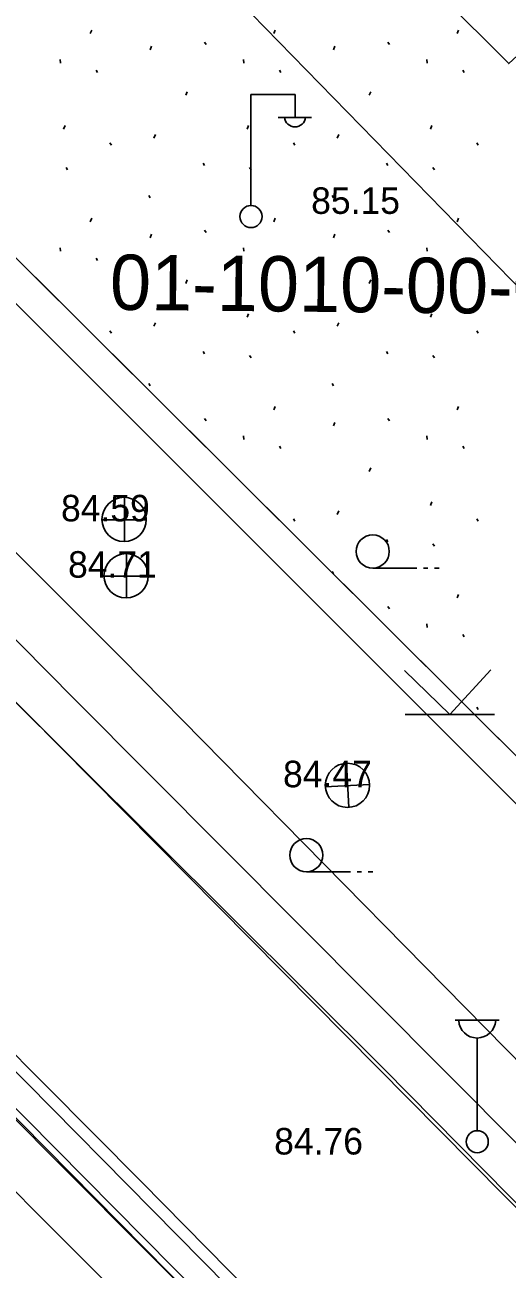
# Model space of a CAD drawing. Extents: x 412225 to 413380, y 4456471 to 4457189.
# Drawn here: x 412345.5 to 412367.3, y 4457046.4 to 4457102.7 of the extents above; entities that cross this region are included whole.
import ezdxf

# ---------------------------------------------------------------- set-up
doc = ezdxf.new("R2010")
doc.units = 0
for name, color, linetype in [('0_HALİHAZIR', 7, 'Continuous'), ('0_KADASTRO', 7, 'Continuous'), ('Level 27', 7, 'Continuous'), ('Level 41', 7, 'Continuous'), ('Level 56', 7, 'Continuous'), ('Level 57', 7, 'Continuous'), ('Level 62', 7, 'Continuous'), ('Level 8', 7, 'Continuous')]:
    doc.layers.add(name, color=color, linetype=linetype)

msp = doc.modelspace()

# ---------------------------------------------------------------- linework, layer by layer
at = {"layer": '0_HALİHAZIR'}
for p, q in [((412355.691, 4457094.546), (412355.691, 4457099.546)), ((412355.691, 4457099.546), (412357.691, 4457099.546)), ((412357.691, 4457098.546), (412357.691, 4457099.546)), ((412356.931, 4457098.506), (412358.431, 4457098.506)), ((412349.974, 4457079.31), (412349.974, 4457081.31)), ((412348.954, 4457080.3), (412350.954, 4457080.3)), ((412350.065, 4457076.761), (412350.065, 4457078.761)), ((412349.045, 4457077.751), (412351.045, 4457077.751)), ((412361.206, 4457078.12), (412363.206, 4457078.12)), ((412363.506, 4457078.12), (412363.706, 4457078.12)), ((412364.006, 4457078.12), (412364.206, 4457078.12)), ((412364.697, 4457071.497), (412362.637, 4457073.487)), ((412364.697, 4457071.497), (412366.547, 4457073.507)), ((412362.677, 4457071.497), (412366.717, 4457071.497)), ((412360.131, 4457067.283), (412360.025, 4457069.28)), ((412359.06, 4457068.218), (412361.057, 4457068.324)), ((412358.204, 4457064.381), (412360.204, 4457064.381)), ((412360.504, 4457064.381), (412360.704, 4457064.381)), ((412361.004, 4457064.381), (412361.204, 4457064.381)), ((412364.931, 4457057.666), (412366.931, 4457057.666)), ((412365.931, 4457052.666), (412365.931, 4457056.859))]:
    msp.add_line(p, q, dxfattribs=at)
for points in [[(412301.706, 4457121.318), (412311.102, 4457113.16), (412330.158, 4457093.729), (412349.865, 4457074.031), (412372.694, 4457050.81), (412390.772, 4457032.428), (412419.372, 4457004.721)], [(412406.259, 4456994.837), (412377.363, 4457023.335), (412350.75, 4457050.347), (412307.137, 4457094.27), (412284.187, 4457117.727)], [(412644.931, 4456753.555), (412630.555, 4456767.782), (412604.684, 4456793.709), (412582.154, 4456816.287), (412559.135, 4456839.628), (412534.75, 4456864.124), (412499.888, 4456899.345), (412487.433, 4456911.736), (412459.99, 4456939.333), (412440.337, 4456959.115), (412419.902, 4456979.921), (412392.691, 4457007.039), (412362.588, 4457037.58), (412334.209, 4457066.321), (412297.701, 4457103.437), (412284.18, 4457117.149)], [(412417.329, 4457002.236), (412381.395, 4457038.35), (412347.738, 4457072.166), (412303.554, 4457116.902)], [(412284.17, 4457116.265), (412296.803, 4457102.771), (412316.426, 4457082.291), (412338.061, 4457060.18), (412363.233, 4457034.899), (412383.867, 4457014.022), (412425.083, 4456972.499), (412446.131, 4456951.075), (412463.226, 4456933.647), (412501.75, 4456894.857), (412523.558, 4456872.918), (412554.446, 4456842.344)], [(412284.13, 4457112.788), (412289.83, 4457106.958), (412301.261, 4457094.649), (412314.468, 4457080.886), (412326.161, 4457068.858), (412338.147, 4457056.814), (412352.735, 4457042.191), (412364.851, 4457029.813), (412379.023, 4457015.687), (412394.281, 4457000.11), (412414.019, 4456980.608)], [(412422.853, 4457032.641), (412406.136, 4457050.742), (412389.41, 4457068.66), (412371.176, 4457087.358), (412353.875, 4457105.109)], [(412340.966, 4457076.102), (412361.717, 4457055.451), (412377.534, 4457039.414), (412399.513, 4457017.111), (412417.007, 4456999.535), (412433.199, 4456983.611)]]:
    msp.add_lwpolyline(points, dxfattribs=at)
for centre, radius in [((412355.701, 4457094.021), 0.5), ((412349.959, 4457080.318), 1), ((412361.206, 4457078.87), 0.75), ((412350.05, 4457077.769), 1), ((412360.062, 4457068.289), 1), ((412358.204, 4457065.131), 0.75), ((412365.931, 4457052.166), 0.5)]:
    msp.add_circle(centre, radius, dxfattribs=at)
for centre, radius, start, end in [((412357.691, 4457098.55), 0.474, 184.8384, 355.1464), ((412365.931, 4457057.695), 0.837, 183.298, 356.9072)]:
    msp.add_arc(centre, radius, start, end, dxfattribs=at)
at = {"layer": '0_KADASTRO'}
msp.add_lwpolyline([(412531.386, 4456906.626), (412255.662, 4457181.172)], dxfattribs=at)
at = {"layer": 'Level 27'}
msp.add_line((412531.386, 4456906.626), (412255.662, 4457181.172), dxfattribs=at)
at = {"layer": 'Level 41'}
for p, q in [((412348.434, 4457102.294), (412348.505, 4457102.453)), ((412356.727, 4457102.294), (412356.798, 4457102.453)), ((412365.02, 4457102.294), (412365.091, 4457102.453)), ((412353.598, 4457101.91), (412353.669, 4457101.803)), ((412361.891, 4457101.91), (412361.962, 4457101.803)), ((412351.133, 4457101.565), (412351.205, 4457101.725)), ((412359.426, 4457101.565), (412359.498, 4457101.725)), ((412347.063, 4457101.119), (412347.081, 4457100.959)), ((412355.356, 4457101.119), (412355.374, 4457100.959)), ((412363.649, 4457101.119), (412363.667, 4457100.959)), ((412348.693, 4457100.649), (412348.763, 4457100.542)), ((412356.986, 4457100.649), (412357.056, 4457100.542)), ((412365.279, 4457100.649), (412365.349, 4457100.542)), ((412352.749, 4457099.505), (412352.821, 4457099.665)), ((412361.042, 4457099.505), (412361.114, 4457099.665)), ((412347.228, 4457097.975), (412347.298, 4457098.135)), ((412355.521, 4457097.975), (412355.591, 4457098.135)), ((412363.814, 4457097.975), (412363.884, 4457098.135)), ((412349.323, 4457097.359), (412349.394, 4457097.253)), ((412351.311, 4457097.567), (412351.382, 4457097.727)), ((412357.616, 4457097.359), (412357.687, 4457097.253)), ((412359.604, 4457097.567), (412359.675, 4457097.727)), ((412365.909, 4457097.359), (412365.98, 4457097.253)), ((412347.337, 4457096.238), (412347.408, 4457096.131)), ((412353.531, 4457096.43), (412353.602, 4457096.323)), ((412355.63, 4457096.238), (412355.701, 4457096.131)), ((412361.824, 4457096.43), (412361.895, 4457096.323)), ((412363.923, 4457096.238), (412363.994, 4457096.131)), ((412351.075, 4457094.977), (412351.146, 4457094.87)), ((412359.368, 4457094.977), (412359.439, 4457094.87)), ((412348.434, 4457093.784), (412348.505, 4457093.943)), ((412356.727, 4457093.784), (412356.798, 4457093.943)), ((412365.02, 4457093.784), (412365.091, 4457093.943)), ((412351.133, 4457093.055), (412351.205, 4457093.215)), ((412353.598, 4457093.4), (412353.669, 4457093.293)), ((412359.426, 4457093.055), (412359.498, 4457093.215)), ((412361.891, 4457093.4), (412361.962, 4457093.293)), ((412347.063, 4457092.609), (412347.081, 4457092.449)), ((412355.356, 4457092.609), (412355.374, 4457092.449)), ((412363.649, 4457092.609), (412363.667, 4457092.449)), ((412348.693, 4457092.139), (412348.763, 4457092.032)), ((412356.986, 4457092.139), (412357.056, 4457092.032)), ((412365.279, 4457092.139), (412365.349, 4457092.032)), ((412352.749, 4457090.995), (412352.821, 4457091.155)), ((412361.042, 4457090.995), (412361.114, 4457091.155)), ((412355.521, 4457089.465), (412355.591, 4457089.625)), ((412363.814, 4457089.465), (412363.884, 4457089.625)), ((412351.311, 4457089.057), (412351.382, 4457089.217)), ((412359.604, 4457089.057), (412359.675, 4457089.217)), ((412349.323, 4457088.849), (412349.394, 4457088.743)), ((412357.616, 4457088.849), (412357.687, 4457088.743)), ((412365.909, 4457088.849), (412365.98, 4457088.743)), ((412353.531, 4457087.92), (412353.602, 4457087.813)), ((412361.824, 4457087.92), (412361.895, 4457087.813)), ((412355.63, 4457087.728), (412355.701, 4457087.621)), ((412363.923, 4457087.728), (412363.994, 4457087.621)), ((412351.075, 4457086.467), (412351.146, 4457086.36)), ((412359.368, 4457086.467), (412359.439, 4457086.36)), ((412356.727, 4457085.274), (412356.798, 4457085.433)), ((412365.02, 4457085.274), (412365.091, 4457085.433)), ((412353.598, 4457084.89), (412353.669, 4457084.783)), ((412359.426, 4457084.545), (412359.498, 4457084.705)), ((412361.891, 4457084.89), (412361.962, 4457084.783)), ((412355.356, 4457084.099), (412355.374, 4457083.939)), ((412363.649, 4457084.099), (412363.667, 4457083.939)), ((412356.986, 4457083.629), (412357.056, 4457083.522)), ((412365.279, 4457083.629), (412365.349, 4457083.522)), ((412361.042, 4457082.485), (412361.114, 4457082.645)), ((412363.814, 4457080.955), (412363.884, 4457081.115)), ((412359.604, 4457080.547), (412359.675, 4457080.707)), ((412357.616, 4457080.339), (412357.687, 4457080.233)), ((412365.909, 4457080.339), (412365.98, 4457080.233)), ((412361.824, 4457079.41), (412361.895, 4457079.303)), ((412363.923, 4457079.218), (412363.994, 4457079.111)), ((412359.368, 4457077.957), (412359.439, 4457077.85)), ((412365.02, 4457076.764), (412365.091, 4457076.923)), ((412361.891, 4457076.38), (412361.962, 4457076.273)), ((412363.649, 4457075.589), (412363.667, 4457075.429)), ((412365.279, 4457075.119), (412365.349, 4457075.012)), ((412365.909, 4457071.829), (412365.98, 4457071.723))]:
    msp.add_line(p, q, dxfattribs=at)
at = {"layer": 'Level 57'}
msp.add_lwpolyline([(412315.011, 4457153.058), (412367.356, 4457100.937), (412369.613, 4457103.012)], dxfattribs=at)
at = {"layer": 'Level 62'}
for p, q in [((412267.88, 4457150.07), (412393.43, 4457023.16)), ((412326.793, 4457071.711), (412497.295, 4456899.362)), ((412327.007, 4457071.922), (412497.51, 4456899.572))]:
    msp.add_line(p, q, dxfattribs=at)
msp.add_lwpolyline([(412284.13, 4457112.788), (412289.83, 4457106.958), (412301.261, 4457094.649), (412314.468, 4457080.886), (412326.161, 4457068.858), (412338.147, 4457056.814), (412352.735, 4457042.191), (412364.851, 4457029.813), (412379.023, 4457015.687), (412394.281, 4457000.11), (412414.019, 4456980.608)], dxfattribs=at)
at = {"layer": 'Level 8'}
msp.add_lwpolyline([(412706.1, 4457175.965), (412751.217, 4457041.463), (412764.575, 4457001.385), (412790.361, 4457003.87), (412821.118, 4456953.851), (412699.954, 4456860.338), (412631.485, 4456804.219), (412585.777, 4456849.927), (412523.439, 4456912.266), (412460.309, 4456974.831), (412403.512, 4457031.625), (412342.192, 4457092.946), (412287.774, 4457146.913), (412253.259, 4457181.199)], dxfattribs=at)

# ---------------------------------------------------------------- texts
at = {"layer": '0_HALİHAZIR'}
for s, p in [('85.15', (412358.422, 4457094.14)), ('84.59', (412347.109, 4457080.23)), ('84.71', (412347.427, 4457077.681)), ('84.47', (412357.15, 4457068.201)), ('84.76', (412356.749, 4457051.588))]:
    msp.add_text(s, height=1.2, dxfattribs=at).set_placement(p)
at = {"layer": 'Level 56'}
msp.add_text('01-1010-00-035/1', height=2.5, rotation=359.4136, dxfattribs=at).set_placement((412349.312, 4457089.805))

doc.saveas('drawing.dxf')
